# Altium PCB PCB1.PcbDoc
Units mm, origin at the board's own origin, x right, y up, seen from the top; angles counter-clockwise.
Board outline 50 x 40 mm, 2 copper layers (Top Layer, Bottom Layer); 8 components, 8 nets, 24 pads, 0 vias.
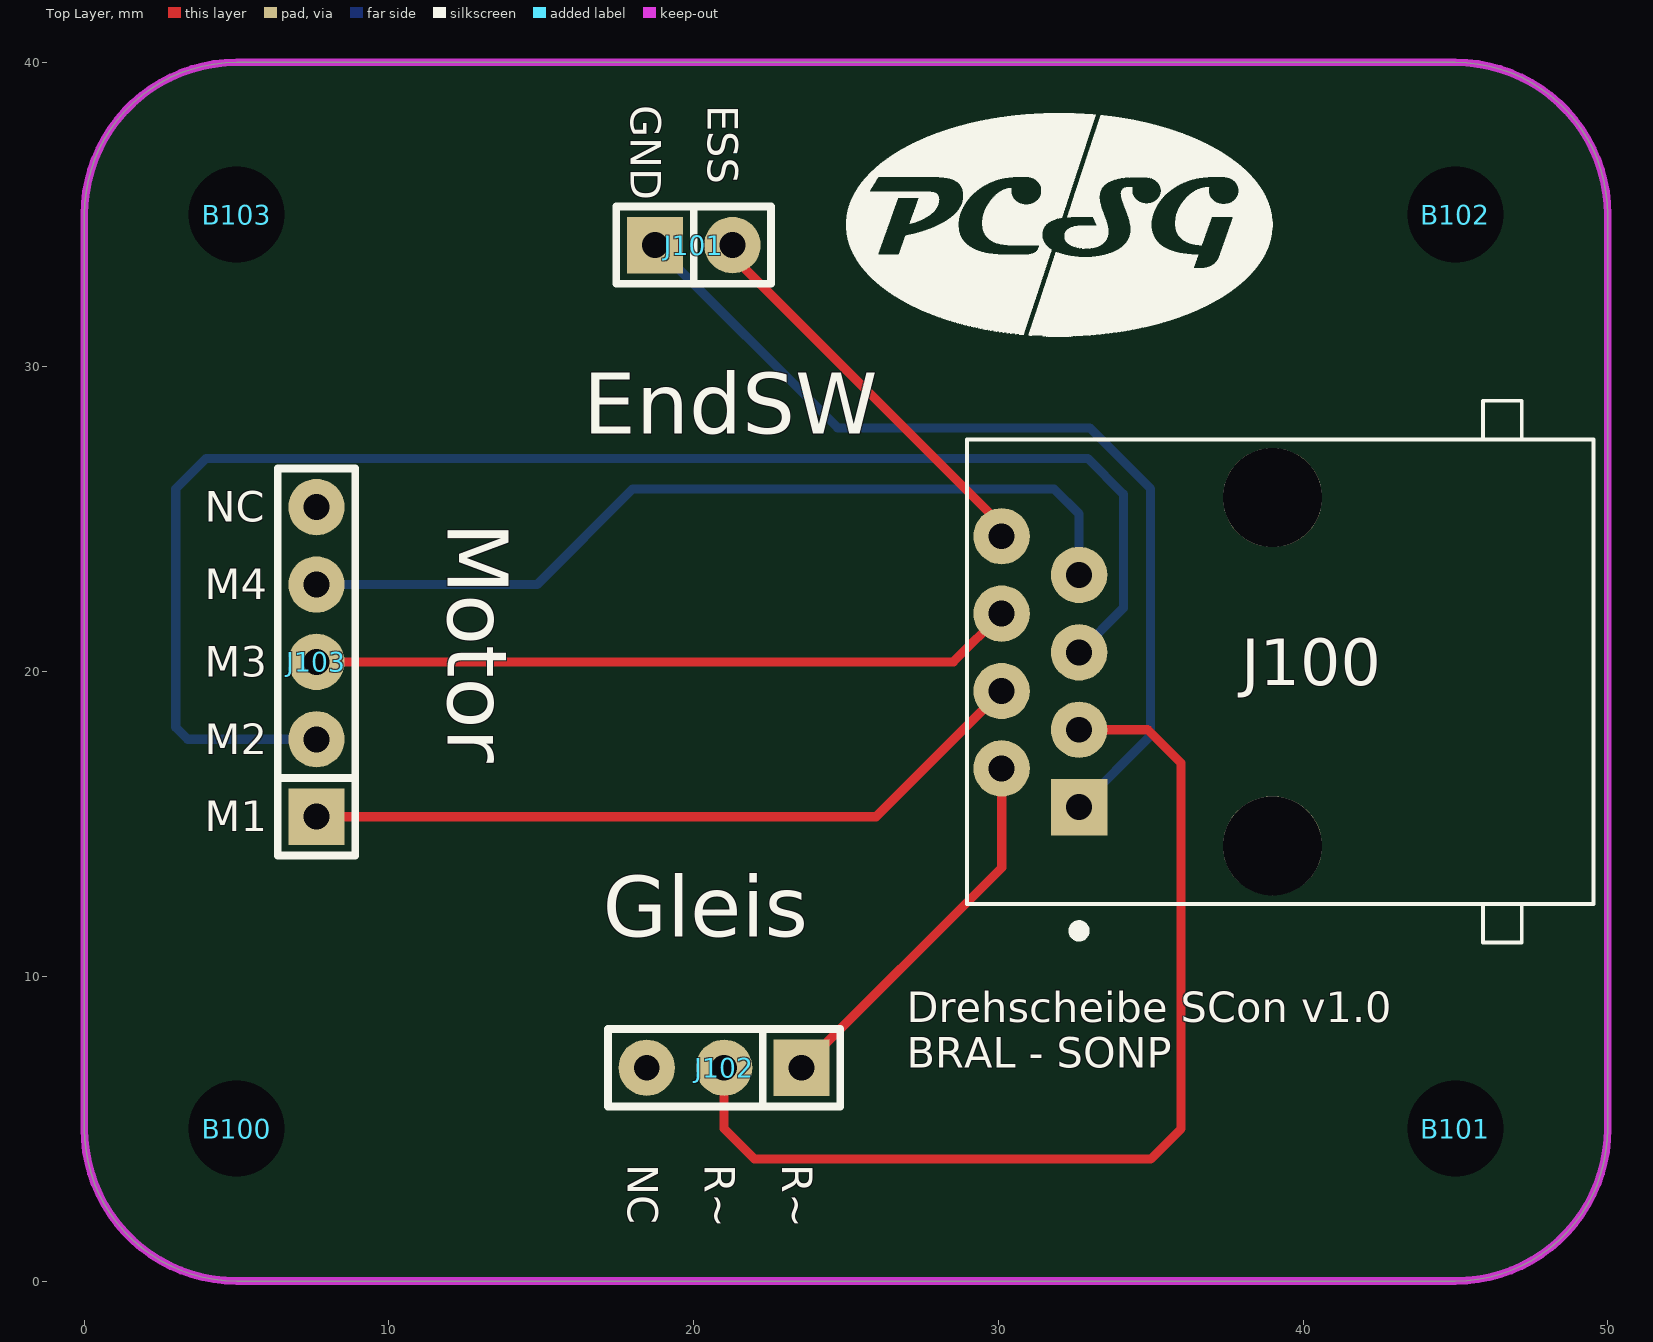
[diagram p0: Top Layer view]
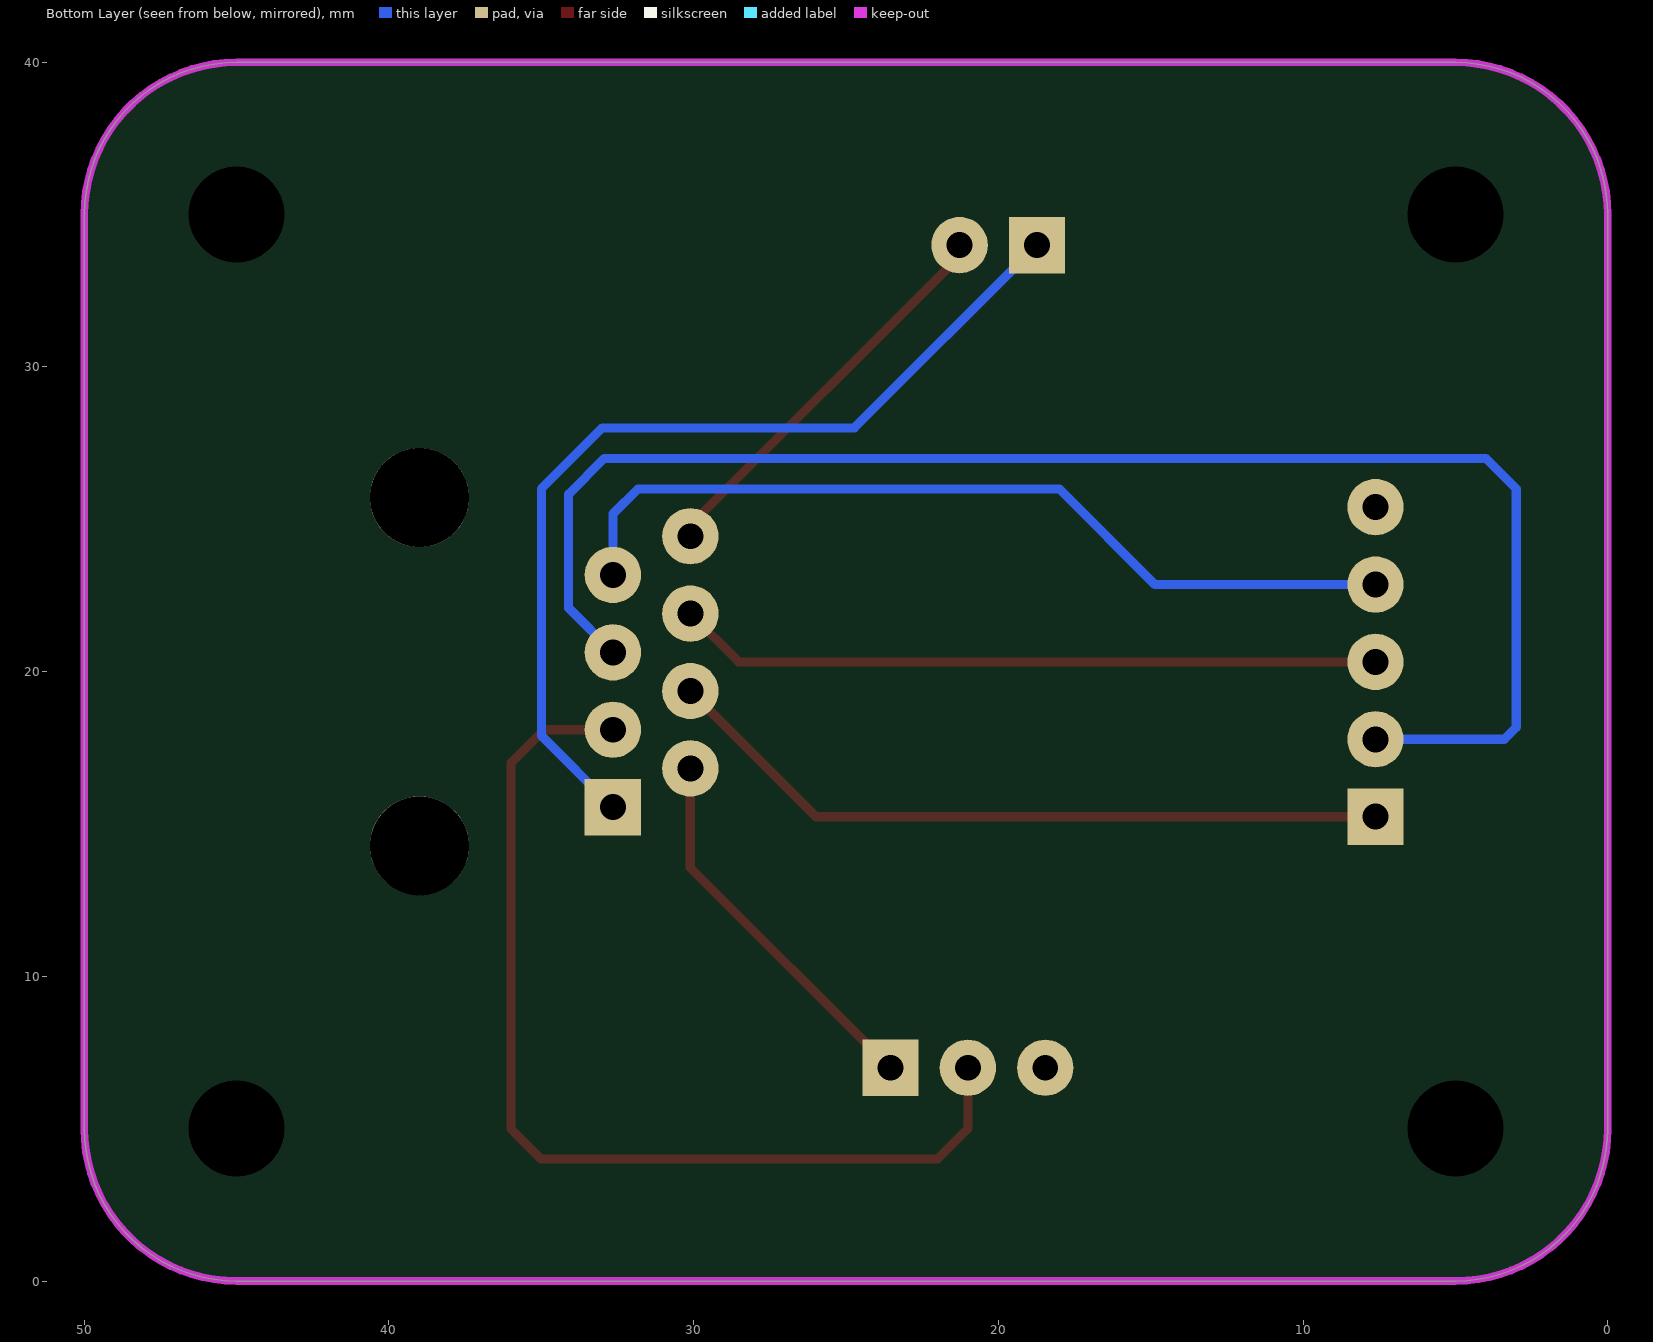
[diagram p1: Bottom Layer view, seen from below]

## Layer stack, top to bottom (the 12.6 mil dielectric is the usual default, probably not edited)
Top Solder: solder mask 0.0102, Solder Resist, Dk 3.5
Top Layer: signal copper 0.0356
Dielectric 1: dielectric 0.32, FR-4, Dk 4.8
Bottom Layer: signal copper 0.0356
Bottom Solder: solder mask 0.0102, Solder Resist, Dk 3.5

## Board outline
0,5 0,35 cw(c5,35) 5,40 45,40 cw(c45,35) 50,35 50,5 cw(c45,5) 45,0 5,0 cw(c5,5)

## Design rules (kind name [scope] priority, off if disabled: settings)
Clearance [All] p1: gap=0.38 ignorepadtopadclearanceinfootprint=FALSE
HoleSize [All] p1: absolutevalues=TRUE maxlimit=4 minlimit=0.3 maxpercent=80.000 minpercent=20.000
MinimumAnnularRing [All] p1: minimumring=0.3
MinimumSolderMaskSliver [All] p1: minsoldermaskwidth=0
PlaneConnect [All] p1: planeconnectstyle=Relief reliefexpansion=0.508 reliefentries=4 reliefconductorwidth=0.3 reliefairgap=0.3
PolygonConnect [All] p1: connectstyle=Relief reliefconductorwidth=0.3 reliefentries=4 polygonreliefangle="90 Angle" airgapwidth=0.3
RoutingVias [All] p1: holewidth=0.55 width=1.1 viastyle="Through Hole" minholewidth=0.5 minwidth=1 maxholewidth=1 maxwidth=2
SilkToSilkClearance [All] p1: silktosilkclearance=0
SilkToSolderMaskClearance [IsPad] p1: minsilkscreentomaskgap=0 clearancetoexposedcopper=TRUE
SolderMaskExpansion [All] p1: expansion=0.102 istentingtop=FALSE
Width [All] p1: maxlimit=1 minlimit=0.2 preferedwidth=0.3
25 further rules are at their usual default settings.

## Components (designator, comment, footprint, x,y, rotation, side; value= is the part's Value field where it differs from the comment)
B100 "Schraube" B_Schraube-M3 5,5 r0 top
B101 "Schraube" B_Schraube-M3 45,5 r0 top
B102 "Schraube" B_Schraube-M3 45,35 r0 top
B103 "Schraube" B_Schraube-M3 5,35 r0 top
J100 "RJ45 Buchse" J_TE-RJ45-8L-B 39,20 r90 top
J101 "SWC" SIP-2 20,34 r0 top
J102 "RLC" Sip-3 21,7 r180 top
J103 "STMC" SIP-5 7.62,20.32 r90 top

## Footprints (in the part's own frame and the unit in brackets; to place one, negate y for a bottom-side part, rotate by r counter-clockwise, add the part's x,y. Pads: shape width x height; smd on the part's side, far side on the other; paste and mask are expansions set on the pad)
B_Schraube-M3 [mm] "LB-2024-04-18"
  round 0.75 hole 3.15 unplated: 1(0,0)
J_TE-RJ45-8L-B [mm] "LB-2024-11-29"
  rect 1.85x1.85 hole 0.85: 1(-4.445,6.35)
  round 1.85 hole 0.85: 2(-3.175,8.89) 3(-1.905,6.35) 4(-0.635,8.89) 5(0.635,6.35) 6(1.905,8.89) 7(3.175,6.35) 8(4.445,8.89)
  round 3.25 hole 3.25 unplated: ""(-5.715,0) ""(5.715,0)
  silkscreen extent -8.89,-10.54 8.89,10.03
SIP-2 [mm] "LB-2024-04-17"
  rect 1.85x1.85 hole 0.85: 1(-1.27,0)
  round 1.85 hole 0.85: 2(1.27,0)
  silkscreen extent -2.54,-1.27 2.54,1.27
Sip-3 [mm] "LB-2024-04-17"
  rect 1.85x1.85 hole 0.85: 1(-2.54,0)
  round 1.85 hole 0.85: 2(0,0) 3(2.54,0)
  silkscreen extent -3.81,-1.27 3.81,1.27
SIP-5 [mm] "LB-2024-04-17"
  rect 1.85x1.85 hole 0.85: 1(-5.08,0)
  round 1.85 hole 0.85: 2(-2.54,0) 3(0,0) 4(2.54,0) 5(5.08,0)
  silkscreen extent -6.35,-1.27 6.35,1.27

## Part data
B100 B101 B102 B103: library part B_Schraube, "Schraubenloch für M3 Schrauben"
J100: library part J_RJ45, "Connector"
J101: library part J_THT_CON2, "Stecker"
J102: library part J_THT_CON3, "Stecker"
J103: library part J_THT_CON5, "Stecker"

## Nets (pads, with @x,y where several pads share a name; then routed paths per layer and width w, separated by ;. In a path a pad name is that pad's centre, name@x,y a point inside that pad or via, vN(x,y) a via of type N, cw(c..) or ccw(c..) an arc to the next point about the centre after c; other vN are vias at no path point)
ESS: J100.8 J101.2 | length 13.2
  Top Layer w0.3: J101.2 21.27,33.642 30.11,24.802 J100.8
GND: J100.1 J101.1 | length 31
  Bottom Layer w0.3: J101.1 24.73,28 33,28 35,26 35,17.905 J100.1
GND-Diff: J100.2 J102.1 | length 12.5
  Top Layer w0.3: J102.1 30.11,13.57 J100.2
M1: J100.4 J103.1 | length 24.2
  Top Layer w0.3: J103.1 25.985,15.24 J100.4
M2: J100.5 J103.2 | length 50.4
  Bottom Layer w0.3: J103.2 3.396,17.78 3,18.176 3,26 4,27 32.929,27 34.105,25.824 34.105,22.09 J100.5
M3: J100.6 J103.3 | length 23.1
  Top Layer w0.3: J103.3 28.525,20.32 J100.6
M4: J100.7 J103.4 | length 28.7
  Bottom Layer w0.3: J103.4 14.86,22.86 18,26 31.824,26 32.65,25.174 J100.7
VCC-Diff: J100.3 J102.2 | length 33.6
  Top Layer w0.3: J102.2 21,5 22,4 35,4 36,5 36,17 34.905,18.095 J100.3
pads on no net: B100.1 B101.1 B102.1 B103.1 J100. J102.3 J103.5

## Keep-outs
Keep-Out Layer:
  the board outline again, w0.254

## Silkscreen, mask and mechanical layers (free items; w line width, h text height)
Top Overlay:
  drawing of 2 lines, arcs and shapes, not listed
  text "GND" at 17.93,38.585 h1 r270
  text "ESS" at 20.47,38.585 h1 r270
  text "EndSW" at 16.375,27.805 h2
  text "NC" at 3.96,24.915 h1
  text "Motor" at 11.93,24.9 h2 r270
  text "M4" at 3.96,22.375 h1
  text "M3" at 3.96,19.835 h1
  text "M2" at 3.96,17.295 h1
  text "M1" at 3.96,14.755 h1
  text "Gleis" at 17.01,11.295 h2
  text "Drehscheibe SCon v1.0 / BRAL - SONP" at 27,7 h1
  text "NC" at 17.829,3.837 h1 r270
  text "R~" at 20.369,3.837 h1 r270
  text "R~" at 22.909,3.837 h1 r270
